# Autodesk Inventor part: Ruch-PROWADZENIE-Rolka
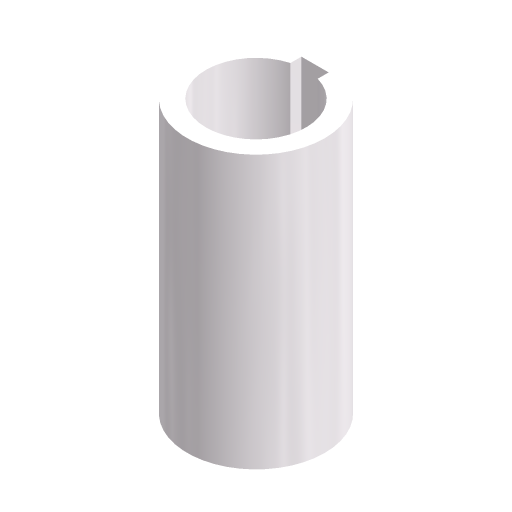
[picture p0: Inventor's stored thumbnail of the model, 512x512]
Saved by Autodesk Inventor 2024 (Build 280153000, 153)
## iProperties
Company: ATC
Created: 2023-03
Part Number: Ruch-PROWADZENIE-Rolka
Document SubType Name: Modeling
Designer: Andrzej Jaskulski
Manufacturer: Standard
Standards Organization: Custom
Material: Kurs-AJ
Stock Number: Ruch-PROWADZENIE-Rolka
Density: 1 g/cm^3
Appearance: Kurs-AJ
Checked By: A.J.
Engr Approved By: Andrzej Jaskulski
Mfg Approved By: Andrzej Jaskulski
Authority: A.J.
DE: 30,000 mm
Title: A.J.: Kurs R2024-MEP
Author: Andrzej Jaskulski
Revision Number: 1/24
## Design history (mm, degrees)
sketch "Szkic1"
  geometry: C1 r 7.56 at (-49.399, 1.842)
  constraints: 1 centre point
extrude "Wyciągnięcie proste1" new body sketch "Szkic1" taper "d1" = 0 deg; distance "DE" = 30
node "Oś"
sketch "Sketch3"
  geometry: L1 (0, 0.275)-(0, 7.56); L2 (-1.5, 6.5)-(1.5, 6.5); L3 (1.5, 6.5)-(1.5, 5.292); L4 (-1.5, 5.292)-(-1.5, 6.5); A1 r 5.5 centre (0, 0) between (-1.5, 5.292) and (1.5, 5.292); 2 further points
  constraints: 8 end point, 2 point on circle, 2 vertical alignment, 1 centre point, 1 coincident, 1 horizontal, 1 midpoint, 1 parallel, 1 perpendicular, 1 vertical, 1 other
  dimensions: "d4" = 3 distance of L2.start L2.end; "d6" = 11 diameter of A1; "d7" = 6.5 distance from line of point (0, 0) L2
extrude "Extrusion3" cut sketch "Sketch3" extent not by distance; stored distance "d8" = 10; taper "d9" = 0 deg
node "Bryła1"
node "Korpusy bryłowe"
node "Korpusy powierzchniowe"
